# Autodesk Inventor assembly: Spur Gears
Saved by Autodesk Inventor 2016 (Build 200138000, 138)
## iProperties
Created: 2016-10
Part Number: Spur Gears
Document SubType Name: Assembly
Designer: Ingenieria
Categories: <?xml version="1.0" encoding="UTF-16"?> <MemberInstance><Categories><FamilyTemplate/><ParamToTemplateMap><ParamToTemplate><ParamToTemplate CategoryParameter="//
ClientObjectVersion: 1
Author: Ingenieria
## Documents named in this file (2)
- C:\Users\ingenieria\Desktop\Project\Enfriador\engranaje central.iam
- C:\Users\ingenieria\Desktop\Project\Enfriador\engranaje_central_1.ipt
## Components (1 placed, 1 different names)
1. Spur Gear2:1
